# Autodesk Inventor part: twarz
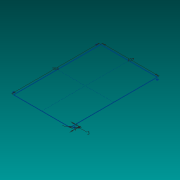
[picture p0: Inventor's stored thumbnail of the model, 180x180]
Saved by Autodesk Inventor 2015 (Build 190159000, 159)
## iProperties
Created: 2016-02
Part Number: twarz
Material: Generic
Document SubType Name: Modeling
Designer: Rafał
Density: 1 g/cm^3
Appearance: Default
Author: Rafał
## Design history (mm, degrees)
sketch "Sketch1"
  geometry: L1 (0, 0)-(-107, 0); L2 (-107, 0)-(-107, 165); L3 (-107, 165)-(0, 165); L4 (0, 165)-(0, 0); L5 (-53.5, 0)-(-53.5, 165); L6 (-107, 82.5)-(0, 82.5); C1 r 1.5 at (4, 4); C2 r 1.5 at (-111, 4); C3 r 1.5 at (4, 161); C4 r 1.5 at (-111, 161)
  constraints: 12 end point, 4 centre point, 4 midpoint, 3 symmetric about line, 2 parallel, 1 horizontal, 1 perpendicular, 3 other
  dimensions: "d0" = 107 distance of L2.end L3.end; "d1" = 165 distance of L1.end L2.end; "d2" = 3 diameter of C1; "d3" = 4 distance from line of L4 C1.centre; "d4" = 4 distance from line of L1 C1.centre
